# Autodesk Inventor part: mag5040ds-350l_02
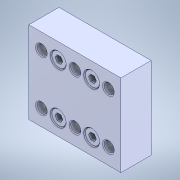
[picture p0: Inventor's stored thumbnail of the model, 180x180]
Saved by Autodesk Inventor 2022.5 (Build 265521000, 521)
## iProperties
Created: 2023-04
Part Number: mag5040ds-350l_02
Material: Generic
Document SubType Name: Modeling
Designer: ImaoCorp
Density: 1 g/cm^3
Appearance: Default
Author: ImaoCorp
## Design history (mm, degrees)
feature "mag5040ds-350l_02"
node "ソリッド1"
